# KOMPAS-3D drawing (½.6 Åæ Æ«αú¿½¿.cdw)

Views: Вид 1
Referenced files in C:\Program Files\ASCON\KOMPAS-3D V10\Sys\: SPDS.lcs, Graphic.lcs
Referenced files in \\F-server\проектирование\Проекты\РЗА и ПА Тюменские РС\4. Проект\ЭП\Туринская\Рабочая документация\: план располодения оборудования на ПС.cdw
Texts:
  Текст на чертеже
  Размерные надписи
  Шероховатость
  Линия-выноска #1
  Линия-выноска #2
  Линия-выноска #3
  Отклонения формы и база
  Заголовок таблицы
  Ячейка таблицы
  Стрелка вида
  Обозначение изменения
  Фигурная скобка
  Номер узла
  Марка координационной оси
  VRCB
  Выносная надпись
  Обозначение узла
  Марка/позиционное обозначение с линией-выноской
  Марка/позиционное обозначение на линии
  Марка/позиционное обозначение без линии-выноски
  Лит-Масса-Масштаб
  Материал-Предприятие
  Title Specification
  Body Specification ( left align )
  Body Specificaton ( centered )
  Без имени
  Normal
  heading 1
  Знак Знак Знак Знак Знак Знак
  Verdana
  Body Text
  MS Sans Serif
  Txt
  Simplex
  TXT
  Обычный
  Термин
  Список определений
  Адрес
  Цитаты
  Форматированный
  Courier New
  Z-конец формы
  Z-начало формы
  Additional DXF text style 0
  Абзац Знак
  Body Text 3
  Title
  ТекстШаг1
  Шрифт 2.5
  Заголовки
  txt
  heading 2
  AGOpus
  footer
  Денис
  RUSTXT
  Обычный (веб)
  ООббыыччнныыйй
  Definition Term
  Definition List
  Address
  Blockquote
  Preformatted
  z-Bottom of Form
  z-Top of Form
  header
  NormalParagraphStyle
  ссылки
  Подпись в квадратике
  табл
  цепи
  Маркировка
  клеммы, контакты
  тексты табл
  Тексты. 3,2
  ЗОНА_привяз
  текст переноса
  ТТееррммиинн
  ССппииссоокк ооппррееддееллеенниийй
  ААддрреесс
  ЦЦииттааттыы
  ФФооррммааттиирроовваанннныыйй
  Z-ккооннеецц ффооррммыы
  Z-ннааччааллоо ффооррммыы
  GOST 2.304 type A
  rustxt
  heading 8
  heading 3
  heading 6
  heading 7
  russ
  heading 4
  heading 5
  heading 9
  HeliosLight
  Pa3
  Pa1
  Три с половиной
  style2
  Table Contents
  Table Heading
  ГОСТ_МНЕ
  ESK - Обозначение
  маркировка
  ISOCP
  ROMANS
  SIMPLEX
  Текст 3,5
  Tahoma
  CNBNDG+TimesNewRoman
  Subtitle
  FR5
  подписи
  Аппараты
  Ссылки
  Состав чартежа
  ячейка табл.
  Пояснения
  Клеммник текст
  .07 RGB_0_0_0 i0b0u0
  CM12
  romans
  текст табл
  Body Text Indent 3
  Основной текст с отступом 3
  gif
  Пояснения 2
  romanc
  eskd1
  Pa15
  Pa18
  ISOCPEUR
  CC С?т?и?л?ь? П?о? ц?е?н?т?р?у?
  Normal (Web)
  ошиновка 110
  лотки
  Экспликация зданий и сооружений
  Номер
  на плане
  Постоянные здания и сооружения
  ОПУ, совмещенный с ЗРУ 10 кВ
  Существующее
  ЗРУ 10 кВ №1
  Трансформатор 1Т, маслоприемник
  Существующий
  Трансформатор 2Т, маслоприемник
  Трансформатор 3Т, маслоприемник
  Временные здания и сооружения
  III
  Вагон-дом для кратковременного отдых рабочих
  Уборная
  Дизельная электростанция
  Контейнеры для ТБО (0,75м 3 )и жидких хоз.-быт.стоков(1м 3 )
  «Екатерина» 9,0х3,0
  Туалетная кабина "Люкс"
  ОАО ПКТИпромстрой
  АДС 45-Т400 РЯ
  Примечания:
  1. Для нужд строительства (размещение задействованного в строительстве персонала, обеспечение
  электроэнергией) использовать временные мобильные инвентарные здания;
  2. При выполнении всех строительно-монтажных работ на площадке необходимо руководствоваться
  требованиями СНиП 12-03-2001 "Безопасность труда в строительстве. Общие требования",
  СНиП 12-04-2002 "Безопасность труда в строительстве. Строительное производство", а также
  ПОТ-РМ-016-2001/РД 153-34.0-03.150-00 "Межотраслевые правила по охране труда (правила
  безопасности) при эксплуатации электроустановок";
  3. Наружное освещение строительной площадки осуществляется за счет существующего освещения;
  4. Под временные сооружения (поз. II, III и IV) устраивается площадка из дорожных плит ПД 60-20 на
  щебеночном основании толщиной 15см;
  5. На период строительства для электроснабжения временных зданий и сооружений использовать ди-
  зельную электростанцию. Прокладку  кабеля от дизельной электростанции до вагончиков выполнить
  в воздушном исполнении в гофрированной трубе диаметром 30 мм, на вагончиках кабель закрепить
  скобами. Щиток временного электроснабжения навесить на стенку вагона-дома для отдыха рабочих;
  6. При выполнении монтажных работ использовать инвентарные лестницы и леса;
  7. Тонкой линией изображено существующее оборудование, замена которого проектом не предусматри-
  вается, утолщенной - вновь устанавливаемое оборудование.
  8. Условные обозначения см. 16/01-ПОС,л.1.
  9. Грузовысотные характеристики КМУ ИНМАН ИМ-150 см. 16/01-ПОС,л.7.
  КМУ ИНМАН ИМ-150
  K5LT_BASIC_RGB_0_0_255_THICK_0.6
  Стили документа
  Бортовой автомобиль КамАЗ 43114-027-02
  АТ ППР#010#0104
  ГИП
  Н.контр.
  Гл.спец.
  Провер.
  Разраб.
  Перезавод ВЛ на ПС Тюмень. Реконструкция устройств
  РЗ и ПА на обратных концах отходящих ВЛ,
  ВОЛС Тюменского ТПО
  ПС 110/10 кВ Торгили
  Матвеев
  Ромин
  Шашерин
  Королева
  Строительный генеральный план
  Общие технические условия на средний ремонт
Dimensions and other numbers on the sheet: 16/01-ПОС; 7; 2,5; 1,8; 2.5; 3,2_; 3.5; 3,2; 2,5 (контакты, клеммы); 3,2 (надписи); 3,2 (Зоны); 5; 2,5_01; 2,5_3; 3,5_01; 3,5_tabl; 5_заголовок; 2,3_; 3,2_зона не привяз; 3,5; 3.2 маркировка; 3,2 элементы; 3,2 линия; 3,2 таблица; 2,5 грязносинь; 2.5 курсив; 2.5_Э5_надписи; 2.5_Э5_ссылки; 2.5_кабель; 3.2; 2.5 надписи; 3 и 5; 5,0_белый_подчёркнутый; 3.2 фиол; 3.2 (текст); 0 i0b0u0; 1; 2; 3; 4; 6; 11,7; 05.13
